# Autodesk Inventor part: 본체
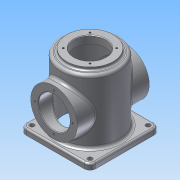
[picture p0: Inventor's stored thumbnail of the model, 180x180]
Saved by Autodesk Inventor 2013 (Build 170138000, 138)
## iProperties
Created: 2015-10
Part Number: 본체
Material: 알루미늄 6061
Document SubType Name: Modeling
Designer: Administrator
Density: 2.71 g/cm^3
Mass: 987.031 g
Surface Area: 1039.63 cm^2
Volume: 364.218 cm^3
Author: Administrator
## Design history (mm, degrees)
sketch "스케치1"
  geometry: L1 (-60, -50)-(60, -50); L2 (60, -50)-(60, -60); L3 (60, -60)-(-60, -60); L4 (-60, -60)-(-60, -50); 2 further points
  constraints: 8 end point, 2 parallel, 1 horizontal, 1 midpoint, 1 perpendicular, 1 vertical alignment
  dimensions: "d0" = 120 distance of L2.end L3.end; "d2" = 10 distance between parallel lines of L3 L1; "d3" = 60 distance from line of L3 point (0, 0)
extrude "돌출1" new body sketch "스케치1" stored distance "d4" = 120; taper "d5" = 0 deg
sketch "스케치2"
  geometry: C1 r 50 at (60, 60); 1 further point
  constraints: 1 centre point, 1 coincident
  dimensions: "d6" = 100 diameter of C1
extrude "돌출2" join sketch "스케치2" distance "d7" = 110; taper "d8" = 0 deg
sketch "스케치3"
  geometry: C1 r 50 at (0, 0) reference; C2 r 40 at (0, 0)
  constraints: 1 centre point, 1 coincident
  dimensions: "d9" = 80 diameter of C2
extrude "돌출3" join sketch "스케치3" distance "d10" = 5; taper "d11" = 0 deg
sketch "스케치5"
  geometry: C1 r 40 at (0, 0); 1 further point
  constraints: 1 centre point, 1 coincident
  dimensions: "d19" = 80 diameter of C1
extrude "돌출4" join sketch "스케치5" stored distance "d20" = 124; taper "d21" = 0 deg
sketch "스케치4"
  geometry: 2 further points
  constraints: 1 coincident
hole "구멍1" sketch "스케치4" at (60, -60) diameter "d12" = 54; stored, may be unused: countersink angle "d16" = 90 deg, drill point angle "d18" = 0 deg; dims "d13" = 6, "d14" = 90, "d15" = 112, "d17" = 125
hole "구멍2" diameter "d24" = 54; stored, may be unused: countersink angle "d28" = 90 deg, drill point angle "d30" = 0 deg; dims "d22" = 10, "d23" = 10, "d25" = 6, "d26" = 90, "d27" = 112, "d29" = 54
sketch "스케치6"
  geometry: C1 r 27 at (0, 0) reference; 1 further point
  constraints: 1 vertical alignment
  dimensions: "d31" = 32.5 distance of C1.centre point (0, 32.5)
hole "구멍3" sketch "스케치6" at (0, 32.5) diameter "d32" = 3.242; stored, may be unused: countersink angle "d36" = 90 deg, drill point angle "d38" = 118 deg; dims "d33" = 8, "d34" = 90, "d35" = 112, "d37" = 10
sketch "스케치7" dims "d43" = 65
  geometry: L1 (0, 0)-(0, 40); L2 (0, 0)-(22.981, 22.981); 2 further points
  constraints: 4 end point, 2 coincident, 1 vertical, 1 vertical alignment, 4 other
  dimensions: "d42" = 45 deg angle of L2 L1
hole "구멍4" sketch "스케치7" at (22.981, 22.981) diameter "d44" = 3.242; stored, may be unused: countersink angle "d48" = 90 deg, drill point angle "d50" = 118 deg; dims "d45" = 8, "d46" = 90, "d47" = 112, "d49" = 10
sketch "스케치8"
  geometry: C1 r 50 at (60, 60) reference; 2 further points
  constraints: 1 horizontal alignment
  dimensions: "d54" = 100 distance of point (110, 110) point (10, 110); "d56" = 50 horizontal distance of C1.centre point (10, 110); "d57" = 50 horizontal distance of C1.centre point (10, 110)
hole "구멍5" sketch "스케치8" at (10, 110), (110, 110) diameter "d58" = 8; stored, may be unused: countersink angle "d62" = 90 deg, drill point angle "d64" = 118 deg; dims "d59" = 8, "d60" = 90, "d61" = 112, "d63" = 10
node "작업 평면1"
sketch "스케치9"
  geometry: L1 (60, 60)-(60, -60) reference; 2 further points
  constraints: 1 horizontal alignment, 1 other
  dimensions: "d66" = 70 distance from line of point (-10, 0) L1
feature "엠보싱1" sketch "스케치9" dims "d0" = 120, "d2" = 10, "d3" = 60, "d67" = 0.5, "d68" = 0
fillet "모깎기1" dims "d69" = 10
chamfer "모따기1" distance "d70" = 3; stored, may be unused: second distance "d71" = 2, angle "d72" = 45 deg
fillet "모깎기2" dims "d73" = 3
fillet "모깎기3" dims "d74" = 5
chamfer "모따기2" distance "d75" = 1; stored, may be unused: second distance "d76" = 2, angle "d77" = 45 deg
chamfer "모따기3" distance "d78" = 1; stored, may be unused: second distance "d79" = 2, angle "d80" = 45 deg
fillet "모깎기4" dims "d81" = 5
fillet "모깎기5" dims "d82" = 3
fillet "모깎기6" dims "d83" = 3
fillet "모깎기7" dims "d84" = 3
node "솔리드1"
pattern_circular "원형 패턴1" dims angle "d40" = 360 deg
mirror "대칭1"
pattern_circular "원형 패턴2" dims angle "d52" = 360 deg
mirror "대칭2"
